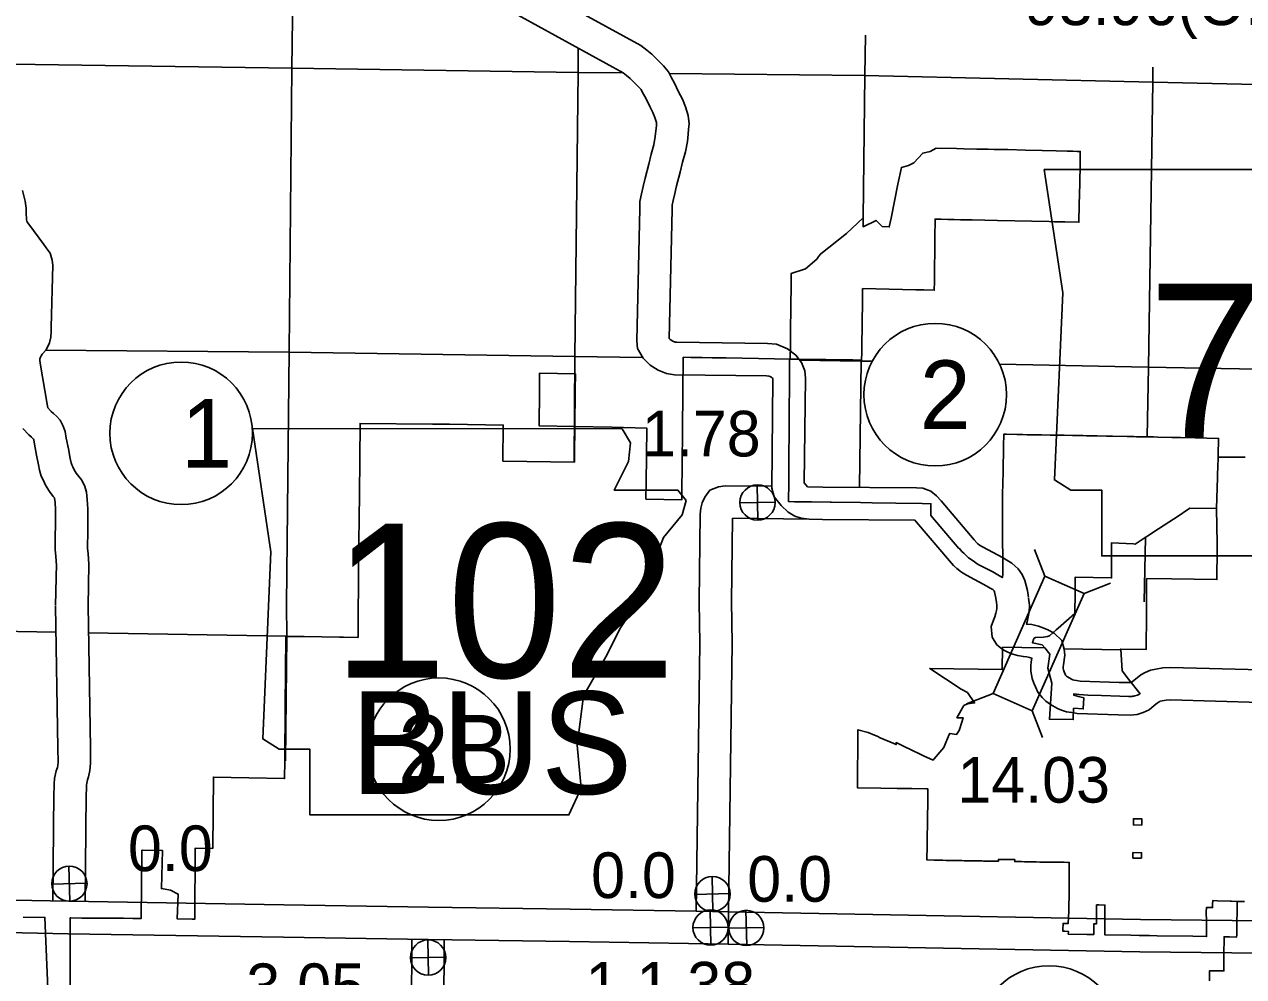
# Model space of a CAD drawing. Extents: x 77230 to 630905, y 790554 to 1662844.
# Drawn here: x 197917 to 220497, y 1585968 to 1603602 of the extents above; entities that cross this region are included whole.
import ezdxf

# ---------------------------------------------------------------- set-up
doc = ezdxf.new("R2010")
doc.units = 0
for name, color, linetype in [('Level 12', 7, 'Continuous'), ('Level 16', 7, 'Continuous'), ('Level 19', 7, 'Continuous'), ('Level 22', 7, 'Continuous'), ('Level 24', 7, 'Continuous'), ('Level 31', 7, 'Continuous'), ('Level 32', 7, 'Continuous'), ('Level 33', 7, 'Continuous'), ('Level 34', 7, 'Continuous')]:
    doc.layers.add(name, color=color, linetype=linetype)

msp = doc.modelspace()

# ---------------------------------------------------------------- linework, layer by layer
at = {"layer": 'Level 12'}
for points in [[(213423, 1597384), (213259, 1597387), (213145, 1597389), (213049, 1597390), (212953, 1597392), (212858, 1597393), (212761, 1597394), (212665, 1597396), (212569, 1597397), (212229, 1597403), (212101, 1597404), (212102, 1597448), (212104, 1597630), (212105, 1597762), (212106, 1597903), (212107, 1597998), (212108, 1598092), (212109, 1598197), (212111, 1598387), (212112, 1598427), (212115, 1598727), (212117, 1598986), (212384, 1599074), (212593, 1599257), (212618, 1599290), (212626, 1599301), (212666, 1599353), (213141, 1599728), (213452, 1600022), (213450, 1599854), (213689, 1599972), (213806, 1599862), (213934, 1599852), (213967, 1600015), (214096, 1600641), (214160, 1600952), (214292, 1600986), (214387, 1601038), (214555, 1601218), (214691, 1601250), (214801, 1601308), (215179, 1601301), (215314, 1601298), (215554, 1601293), (215661, 1601291), (215768, 1601289), (215875, 1601287), (216128, 1601282), (216132, 1601282), (216460, 1601274), (216769, 1601266), (217023, 1601260), (217231, 1601255), (217333, 1601252), (217415, 1601250), (217470, 1601249), (217468, 1601019), (217461, 1600655), (217453, 1600264), (217447, 1599939), (217184, 1599944), (217165, 1599945), (216996, 1599948), (216896, 1599950), (215937, 1599970), (215467, 1599980), (215346, 1599983), (215251, 1599985), (215137, 1599987), (215022, 1599990), (214895, 1599992), (214783, 1599995), (214783, 1599935), (214782, 1599895), (214781, 1599747), (214779, 1599598), (214778, 1599532), (214778, 1599449), (214776, 1599301), (214775, 1599190), (214774, 1599131), (214774, 1599094), (214771, 1598858), (214771, 1598839), (214769, 1598680), (214576, 1598684), (214427, 1598688), (213439, 1598710), (213436, 1598348), (213434, 1598194), (213434, 1598101), (213433, 1598046), (213432, 1598008), (213431, 1597915), (213429, 1597770), (213427, 1597636), (213425, 1597522), (213423, 1597389)], [(208112, 1596158), (207448, 1596170), (207455, 1596818), (207458, 1597144), (208122, 1597132), (208118, 1596835), (208118, 1596808)], [(218614, 1588772), (218614, 1588828), (218615, 1588888), (218457, 1588891), (218457, 1588868), (218456, 1588831), (218455, 1588776)], [(218606, 1588160), (218607, 1588232), (218607, 1588261), (218448, 1588265), (218446, 1588170), (218446, 1588164)]]:
    msp.add_lwpolyline(points, close=True, dxfattribs=at)
for points in [[(208112, 1596158), (208794, 1596141), (209445, 1596124), (209432, 1595105), (209428, 1594810), (210090, 1594797), (210091, 1594854), (210092, 1594965), (210097, 1595436), (210104, 1596114), (210111, 1596773), (210118, 1597439), (210262, 1597436), (210472, 1597432), (210655, 1597429), (210773, 1597426), (210814, 1597426), (210915, 1597424), (211807, 1597408), (212086, 1597402), (212085, 1597136), (212084, 1597033), (212081, 1596338), (212079, 1596082), (212079, 1596051), (212076, 1595604), (212074, 1595123), (212071, 1594764), (212180, 1594763), (212295, 1594761), (212497, 1594759), (212838, 1594755), (212863, 1594754), (213402, 1594748), (213620, 1594744), (214057, 1594736), (214545, 1594727), (214706, 1594724), (214706, 1594636), (214705, 1594510), (215225, 1593897), (215229, 1593901), (215280, 1593841), (215315, 1593810), (215404, 1593721), (215467, 1593679), (215581, 1593600), (215855, 1593462), (215976, 1593392), (216030, 1593358), (216037, 1593422), (216035, 1593784), (216033, 1594004), (216033, 1594055), (216031, 1594297), (216030, 1594455), (216030, 1594601), (216029, 1594639), (216029, 1594700), (216033, 1594905), (216036, 1595102), (216041, 1595322), (216042, 1595372), (216043, 1595419), (216048, 1595686), (216050, 1595790), (216054, 1596012), (216105, 1596011), (216297, 1596008), (216410, 1596006), (216488, 1596004), (216684, 1596001), (216753, 1596000), (216912, 1595997), (216954, 1595997), (216970, 1595996), (217017, 1595995), (217075, 1595994), (217176, 1595993), (217326, 1595990), (217518, 1595987), (217587, 1595985), (217671, 1595984), (217786, 1595981), (217958, 1595978), (218066, 1595976), (218339, 1595971), (218463, 1595968), (218512, 1595967), (218719, 1595963), (218763, 1595962), (218827, 1595961), (218911, 1595959), (219166, 1595954), (219185, 1595953), (219327, 1595950), (219599, 1595944), (220034, 1595935), (220025, 1595619), (220024, 1595588)], [(198763, 1585741), (198763, 1586404), (198763, 1587054), (198780, 1587054), (198979, 1587053), (199093, 1587052), (199302, 1587051), (199421, 1587050), (199750, 1587048), (199924, 1587047), (200080, 1587046), (200093, 1588307), (200102, 1588307), (200474, 1588305), (200456, 1587598), (200621, 1587568), (200762, 1587498), (200748, 1587036), (201022, 1587031), (201073, 1587030), (201078, 1588346), (201406, 1588342), (201419, 1589664), (202076, 1589650), (202737, 1589636), (202740, 1589969), (202747, 1590970), (202762, 1592269), (203425, 1592259), (203829, 1592253), (204098, 1592249), (204101, 1592758), (204104, 1593171), (204106, 1593576), (204125, 1594899), (204129, 1595549), (204133, 1596212), (205473, 1596201), (205790, 1596196), (206455, 1596187), (206786, 1596182), (206778, 1595514), (208105, 1595492), (208107, 1595685), (208111, 1596094), (208112, 1596158)], [(220024, 1595588), (220018, 1595390), (220015, 1595286), (220013, 1595213), (219997, 1594636), (219503, 1594642), (219245, 1594473), (219197, 1594442), (219027, 1594330), (218919, 1594260), (218724, 1594132), (218706, 1594120), (218675, 1594099), (218490, 1593979), (218460, 1593980), (218051, 1594004), (218051, 1593888), (218052, 1593352), (217377, 1593364), (217375, 1593084), (217372, 1592690), (217063, 1592421), (217025, 1592388), (216901, 1592280), (216862, 1592266), (216791, 1592255), (216643, 1592249), (216616, 1592234), (216608, 1592212), (216585, 1592152), (216585, 1592152), (216768, 1592112), (216814, 1592057), (216389, 1592063), (216032, 1592069), (216026, 1591658), (214685, 1591676), (215266, 1591289), (215384, 1591227), (215514, 1591037), (215382, 1591019), (215317, 1590986), (215186, 1590761), (215304, 1590759), (215242, 1590565), (215229, 1590524), (215180, 1590454), (215055, 1590473), (215045, 1590452), (214984, 1590306), (214943, 1590208), (214872, 1590127), (214764, 1589999), (214745, 1589977), (214568, 1590058), (214522, 1590080), (214494, 1590093), (214363, 1590157), (214197, 1590237), (214061, 1590303), (214063, 1590264), (214016, 1590285), (213769, 1590393), (213721, 1590413), (213708, 1590419), (213659, 1590439), (213546, 1590487), (213354, 1590541), (213351, 1590147), (213349, 1589818), (213347, 1589463), (213778, 1589457), (214078, 1589453), (214354, 1589449), (214623, 1589446), (214651, 1589445), (214649, 1589338), (214648, 1589275), (214647, 1589211), (214646, 1589148), (214646, 1589086), (214645, 1589022), (214644, 1588959), (214643, 1588896), (214642, 1588833), (214641, 1588790), (214641, 1588770), (214640, 1588723), (214640, 1588707), (214639, 1588644), (214638, 1588581), (214637, 1588517), (214636, 1588454), (214635, 1588391), (214634, 1588332), (214634, 1588303), (214632, 1588223), (214632, 1588130), (214766, 1588127), (214859, 1588124)], [(220006, 1593737), (220008, 1593891), (220009, 1593987), (219997, 1594636), (220013, 1595213), (220015, 1595286), (220018, 1595390), (220024, 1595588), (220323, 1595589), (220528, 1595589)], [(214639, 1588644), (214640, 1588707), (214640, 1588723), (214641, 1588770), (214641, 1588790), (214642, 1588833), (214643, 1588896), (214644, 1588959), (214645, 1589022), (214646, 1589086), (214646, 1589148), (214647, 1589211), (214648, 1589275), (214649, 1589338), (214651, 1589445), (214623, 1589446), (214354, 1589449), (214078, 1589453), (213778, 1589457), (213347, 1589463), (213349, 1589818), (213351, 1590147), (213354, 1590541), (213546, 1590487), (213659, 1590439), (213708, 1590419), (213721, 1590413), (213769, 1590393), (214016, 1590285), (214063, 1590264), (214061, 1590303), (214197, 1590237), (214363, 1590157), (214494, 1590093), (214522, 1590080), (214568, 1590058), (214745, 1589977), (214764, 1589999), (214872, 1590127), (214943, 1590208), (214984, 1590306), (215045, 1590452), (215055, 1590473), (215180, 1590454), (215229, 1590524), (215242, 1590565), (215304, 1590759), (215186, 1590761), (215317, 1590986), (215382, 1591019), (215514, 1591037), (215384, 1591227), (215266, 1591289), (214685, 1591676), (216026, 1591658), (216032, 1592069), (216389, 1592063), (216814, 1592057), (216906, 1591937), (216870, 1591681), (216943, 1591404), (216899, 1590735), (217343, 1590728), (217347, 1590938), (217528, 1590926), (217536, 1591131), (217437, 1591158), (217351, 1591181), (217352, 1591203), (217449, 1591190), (217614, 1591183), (217866, 1591173), (218206, 1591161), (218368, 1591154), (218379, 1591154), (218394, 1591154), (218409, 1591155), (218427, 1591157), (218446, 1591159), (218465, 1591163), (218480, 1591166), (218507, 1591174), (218531, 1591183), (218556, 1591195), (218578, 1591206), (218579, 1591207), (218368, 1591474), (218246, 1591629), (218222, 1592034), (218690, 1592025), (218696, 1592694), (218697, 1592857), (218701, 1593340), (219160, 1593334), (220002, 1593321), (220002, 1593362), (220003, 1593467), (220004, 1593557), (220005, 1593647), (220006, 1593737)], [(217250, 1586755), (217251, 1586805), (217251, 1586806), (217184, 1586807), (217149, 1586808), (217150, 1586843), (217153, 1586953), (217250, 1586954), (217258, 1587180), (217260, 1587264), (217262, 1587303), (217263, 1587338), (217266, 1587411), (217269, 1587484), (217269, 1587554), (217269, 1587584), (217269, 1587626), (217269, 1587684), (217269, 1587700), (217269, 1587768), (217269, 1587784), (217269, 1587843), (217269, 1587884), (217269, 1587915), (217269, 1587984), (217269, 1588017), (217269, 1588084), (217239, 1588084), (217174, 1588085), (217158, 1588085), (217109, 1588086), (217076, 1588086), (217043, 1588086), (217005, 1588087), (216979, 1588087), (216935, 1588087), (216915, 1588086), (216864, 1588088), (216849, 1588088), (216793, 1588089), (216785, 1588089), (216722, 1588090), (216720, 1588090), (216655, 1588092), (216652, 1588092), (216590, 1588093), (216581, 1588093), (216523, 1588094), (216510, 1588095), (216453, 1588096), (216439, 1588096), (216384, 1588097), (216368, 1588097), (216319, 1588098), (216297, 1588099), (216257, 1588099), (216257, 1588136), (216227, 1588136), (216184, 1588137), (216156, 1588137), (216117, 1588137), (216058, 1588138), (216029, 1588139), (215957, 1588140), (215957, 1588106), (215892, 1588105), (215807, 1588105), (215780, 1588107), (215759, 1588107), (215714, 1588109), (215679, 1588109), (215648, 1588110), (215602, 1588111), (215582, 1588111), (215519, 1588111), (215452, 1588113), (215439, 1588113), (215386, 1588114), (215359, 1588114), (215320, 1588115), (215279, 1588116), (215253, 1588117), (215192, 1588117), (215187, 1588117), (215157, 1588117), (215123, 1588118), (215058, 1588119), (214990, 1588121), (214925, 1588123), (214859, 1588124), (214766, 1588127), (214632, 1588130), (214632, 1588223), (214634, 1588303), (214634, 1588332), (214635, 1588391), (214636, 1588454), (214637, 1588517), (214638, 1588581), (214639, 1588644)], [(214859, 1588124), (214925, 1588123), (214990, 1588121), (215058, 1588119), (215123, 1588118), (215157, 1588117), (215187, 1588117), (215192, 1588117), (215253, 1588117), (215279, 1588116), (215320, 1588115), (215359, 1588114), (215386, 1588114), (215439, 1588113), (215452, 1588113), (215519, 1588111), (215582, 1588111), (215602, 1588111), (215648, 1588110), (215679, 1588109), (215714, 1588109), (215759, 1588107), (215780, 1588107), (215807, 1588105), (215892, 1588105), (215957, 1588106), (215957, 1588140), (216029, 1588139), (216058, 1588138), (216117, 1588137), (216156, 1588137), (216184, 1588137), (216227, 1588136), (216257, 1588136), (216257, 1588099), (216297, 1588099), (216319, 1588098), (216368, 1588097), (216384, 1588097), (216439, 1588096), (216453, 1588096), (216510, 1588095), (216523, 1588094), (216581, 1588093), (216590, 1588093), (216652, 1588092), (216655, 1588092), (216720, 1588090), (216722, 1588090), (216785, 1588089), (216793, 1588089), (216849, 1588088), (216864, 1588088), (216915, 1588086), (216935, 1588087), (216979, 1588087), (217005, 1588087), (217043, 1588086), (217076, 1588086), (217109, 1588086), (217158, 1588085), (217174, 1588085), (217239, 1588084), (217269, 1588084), (217269, 1588017), (217269, 1587984), (217269, 1587915), (217269, 1587884), (217269, 1587843), (217269, 1587784), (217269, 1587768), (217269, 1587700), (217269, 1587684), (217269, 1587626), (217269, 1587584), (217269, 1587554), (217269, 1587484), (217266, 1587411), (217263, 1587338), (217262, 1587303), (217260, 1587264), (217258, 1587180), (217250, 1586954), (217153, 1586953), (217150, 1586843), (217149, 1586808), (217184, 1586807), (217251, 1586806), (217251, 1586805), (217250, 1586755), (217596, 1586748), (217721, 1586746), (217722, 1586944), (217771, 1586943), (217771, 1587022), (217772, 1587122), (217773, 1587297), (217818, 1587296), (217818, 1587296), (217918, 1587294)], [(220511, 1587357), (220459, 1587359), (220380, 1587361), (220373, 1587361), (220273, 1587364), (220247, 1587365), (220012, 1587372), (219924, 1587375), (219922, 1587309), (219921, 1587246), (219824, 1587248), (219807, 1587245), (219806, 1587165), (219806, 1587155), (219808, 1587000), (219810, 1586711), (219554, 1586715), (218896, 1586725), (218756, 1586728), (218598, 1586730), (218562, 1586731), (218409, 1586734), (217924, 1586742), (217925, 1586941), (217926, 1587008), (217926, 1587008), (217927, 1587115), (217927, 1587118), (217927, 1587199), (217928, 1587294), (217918, 1587294), (217818, 1587296), (217818, 1587296), (217773, 1587297), (217772, 1587122), (217771, 1587022), (217771, 1586943), (217722, 1586944), (217721, 1586746), (217596, 1586748), (217250, 1586755)], [(217918, 1587294), (217928, 1587294), (217927, 1587199), (217927, 1587118), (217927, 1587115), (217926, 1587008), (217926, 1587008), (217925, 1586941), (217924, 1586742), (218409, 1586734), (218562, 1586731), (218598, 1586730), (218756, 1586728), (218896, 1586725), (219554, 1586715), (219810, 1586711), (219808, 1587000), (219806, 1587155), (219806, 1587165), (219807, 1587245), (219824, 1587248), (219921, 1587246), (219922, 1587309), (219924, 1587375), (220012, 1587372), (220247, 1587365), (220273, 1587364), (220373, 1587361), (220380, 1587361), (220370, 1586791), (220369, 1586741), (220368, 1586700), (220235, 1586703), (220134, 1586705), (220131, 1586360), (220132, 1586075), (219866, 1586077), (219865, 1585890)], [(197896, 1587071), (198296, 1587064), (198352, 1585750)]]:
    msp.add_lwpolyline(points, dxfattribs=at)
at = {"layer": 'Level 16'}
for points in [[(202774, 1592862), (202822, 1597553), (202869, 1602788), (202947, 1608360)], [(213449, 1600020), (213483, 1602656), (213494, 1603402)], [(208173, 1603158), (208172, 1602708), (208112, 1597445), (208096, 1595493)], [(197244, 1602871), (202871, 1602794), (208170, 1602710), (209003, 1602702)], [(218817, 1602810), (218813, 1602532), (218735, 1597256), (218712, 1595964)], [(209864, 1602693), (213477, 1602658), (218819, 1602534), (220731, 1602490)], [(198311, 1597567), (202822, 1597535), (208110, 1597451), (209359, 1597431)], [(212263, 1597386), (213411, 1597368), (213616, 1597364)], [(213385, 1595036), (213415, 1597368), (213415, 1597385)], [(215983, 1597312), (218725, 1597252), (220761, 1597220)], [(218679, 1594102), (218657, 1592906)], [(202754, 1589967), (202779, 1592266), (202774, 1592862)], [(198505, 1592347), (197072, 1592372)], [(204077, 1592249), (202769, 1592272), (199107, 1592336)], [(218222, 1592022), (217165, 1592041)]]:
    msp.add_lwpolyline(points, dxfattribs=at)
at = {"layer": 'Level 19'}
for p, q in [((216817, 1593385), (216626, 1593877)), ((217542, 1593065), (218034, 1593256)), ((215858, 1591211), (215366, 1591020)), ((216583, 1590891), (216774, 1590399))]:
    msp.add_line(p, q, dxfattribs=at)
msp.add_lwpolyline([(216583, 1590891), (217542, 1593065), (216817, 1593385), (215858, 1591211)], close=True, dxfattribs=at)
at = {"layer": 'Level 22'}
msp.add_line((212186, 1594497), (212300, 1594458), dxfattribs=at)
for points in [[(206785, 1604611), (209334, 1603210), (209446, 1603124), (209538, 1603048), (209652, 1602936), (209753, 1602834), (209848, 1602721), (209899, 1602614), (209957, 1602512), (210033, 1602354), (210104, 1602218), (210158, 1602078), (210212, 1601915), (210230, 1601763), (210219, 1601659), (210210, 1601567), (210195, 1601434), (210158, 1601239), (210107, 1601051), (210062, 1600866), (209994, 1600611), (209963, 1600469), (209934, 1600340), (209916, 1600253), (209914, 1600174), (209861, 1597783), (209879, 1597766), (209928, 1597735), (209968, 1597719), (209998, 1597715), (211678, 1597691), (211848, 1597682), (212052, 1597593), (212203, 1597474), (212306, 1597339), (212369, 1597186), (212381, 1597052), (212361, 1595115), (212422, 1595040)], [(206487, 1604091), (209005, 1602706), (209071, 1602656), (209135, 1602602), (209230, 1602510), (209310, 1602429), (209339, 1602394), (209365, 1602338), (209425, 1602233), (209498, 1602083), (209556, 1601972), (209592, 1601876), (209623, 1601783), (209626, 1601759), (209622, 1601722), (209613, 1601630), (209601, 1601523), (209572, 1601374), (209525, 1601200), (209480, 1601013), (209411, 1600754), (209377, 1600599), (209347, 1600464), (209318, 1600323), (209314, 1600190), (209260, 1597744), (209271, 1597602), (209374, 1597420), (209509, 1597289), (209652, 1597201), (209809, 1597134), (209954, 1597115), (211659, 1597091), (211709, 1597088), (211741, 1597074), (211772, 1597050), (211779, 1597040), (211780, 1597029), (211760, 1595016), (211802, 1594851), (211932, 1594691), (212064, 1594569), (212186, 1594497)], [(199112, 1593603), (199096, 1593795), (199088, 1593903), (199087, 1593997), (199089, 1594132), (199094, 1594304), (199092, 1594631), (199082, 1594802), (199068, 1594939), (199038, 1595042), (198979, 1595159), (198923, 1595229), (198878, 1595290), (198836, 1595355), (198812, 1595409), (198793, 1595447), (198783, 1595485), (198767, 1595564), (198732, 1595742), (198693, 1595940), (198671, 1596065), (198635, 1596162), (198581, 1596270), (198512, 1596346), (198457, 1596398), (198415, 1596436), (198350, 1596503), (198336, 1596568), (198216, 1597294), (198205, 1597376), (198205, 1597406), (198207, 1597420), (198216, 1597442), (198229, 1597467), (198248, 1597494), (198320, 1597575), (198381, 1597703), (198405, 1597811), (198412, 1597912), (198414, 1597998), (198444, 1599140), (198432, 1599234), (198393, 1599367), (198318, 1599463), (198278, 1599524), (197999, 1599900), (197972, 1599935), (197972, 1599936), (197965, 1599955), (197958, 1599982), (197954, 1600015), (197950, 1600086), (197947, 1600200), (197930, 1600327), (197882, 1600528)], [(198513, 1593581), (198498, 1593746), (198488, 1593879), (198487, 1593997), (198489, 1594143), (198494, 1594311), (198492, 1594612), (198484, 1594754), (198477, 1594823), (198472, 1594832), (198448, 1594862), (198384, 1594949), (198305, 1595071), (198268, 1595157), (198230, 1595234), (198199, 1595344), (198179, 1595446), (198143, 1595627), (198104, 1595829), (198089, 1595908), (198084, 1595923), (198082, 1595927), (198049, 1595958), (197998, 1596004), (197888, 1596118)], [(211769, 1595048), (210896, 1595056), (210772, 1595037), (210614, 1594977), (210516, 1594847), (210468, 1594740), (210446, 1594641), (210435, 1594533), (210414, 1592917)], [(212422, 1595040), (212706, 1595034), (214440, 1595018), (214558, 1595011), (214706, 1594956), (214811, 1594870), (214893, 1594778), (215508, 1594055), (215556, 1594000), (215573, 1593983), (215606, 1593958), (215661, 1593926), (216041, 1593722), (216112, 1593679), (216205, 1593624), (216322, 1593522), (216395, 1593412), (216448, 1593305), (216472, 1593213), (216495, 1593121), (216514, 1592988)], [(212454, 1594441), (211034, 1594455), (211014, 1592909)], [(212300, 1594458), (212450, 1594439), (212697, 1594434), (214410, 1594418), (214441, 1594383), (215053, 1593665), (215122, 1593584), (215185, 1593525), (215272, 1593459), (215366, 1593403), (215744, 1593200), (215805, 1593163), (215852, 1593135), (215868, 1593121), (215875, 1593111), (215883, 1593095), (215891, 1593064), (215905, 1593007), (215920, 1592904)], [(198512, 1593615), (198496, 1592840)], [(199112, 1593603), (199096, 1592828)], [(210415, 1592908), (210428, 1592139), (210358, 1587179), (208024, 1587217), (205404, 1587257), (202724, 1587298), (198741, 1587363), (197026, 1587396)], [(198496, 1592829), (198539, 1590196), (198542, 1589940), (198537, 1589878), (198529, 1589843), (198505, 1589781), (198476, 1589635), (198468, 1589540), (198468, 1589464), (198460, 1589368), (198445, 1587373)], [(199096, 1592839), (199139, 1590204), (199142, 1589920), (199132, 1589786), (199104, 1589669), (199084, 1589615), (199071, 1589548), (199068, 1589515), (199068, 1589443), (199060, 1589343), (199045, 1587358)], [(211014, 1592918), (211028, 1592140), (210955, 1587168)], [(220809, 1591047), (219141, 1591091), (219063, 1591089), (218988, 1591075), (218952, 1591068), (218943, 1591064), (218930, 1591056), (218899, 1591032), (218843, 1590986), (218746, 1590911), (218637, 1590860), (218525, 1590825), (218404, 1590811), (218175, 1590817), (217414, 1590843), (217313, 1590859), (217216, 1590872), (217126, 1590904), (217051, 1590934), (216918, 1591010), (216836, 1591066), (216766, 1591135), (216689, 1591235), (216641, 1591332), (216614, 1591404), (216582, 1591491), (216558, 1591622), (216558, 1591725), (216563, 1591800), (216572, 1591866), (216534, 1591878), (216481, 1591891), (216419, 1591896), (216310, 1591915), (216221, 1591942), (216143, 1591969), (216041, 1592021), (215928, 1592114), (215843, 1592255), (215823, 1592449), (215865, 1592567), (215887, 1592633), (215908, 1592699), (215919, 1592746), (215926, 1592788), (215928, 1592828), (215919, 1592914)], [(220825, 1591647), (219143, 1591691), (219002, 1591688), (218873, 1591664), (218774, 1591643), (218675, 1591602), (218593, 1591554), (218524, 1591501), (218468, 1591455), (218431, 1591426), (218420, 1591420), (218401, 1591415), (218377, 1591412), (218192, 1591417), (217472, 1591441), (217401, 1591452), (217359, 1591458), (217337, 1591466), (217312, 1591476), (217236, 1591519), (217219, 1591531), (217217, 1591533), (217201, 1591553), (217192, 1591571), (217175, 1591615), (217163, 1591649), (217158, 1591677), (217158, 1591706), (217160, 1591739), (217185, 1591923), (217175, 1592029), (217133, 1592190), (216987, 1592329), (216873, 1592390), (216796, 1592423), (216700, 1592455), (216577, 1592486), (216495, 1592492), (216473, 1592496), (216487, 1592540), (216508, 1592628), (216524, 1592723), (216529, 1592847), (216515, 1592978)], [(210955, 1587168), (210358, 1587179)], [(210955, 1587168), (210949, 1586568)], [(220853, 1587001), (218587, 1587027), (213297, 1587124), (210955, 1587168)], [(210949, 1586569), (208015, 1586617), (205395, 1586657), (202714, 1586699), (198730, 1586763), (197017, 1586796)], [(205093, 1586286), (205091, 1586665)], [(205693, 1586288), (205691, 1586660)], [(220846, 1586401), (218578, 1586427), (213286, 1586524), (210950, 1586568)], [(205071, 1584549), (205093, 1586291)], [(205671, 1584541), (205693, 1586283)]]:
    msp.add_lwpolyline(points, dxfattribs=at)
at = {"layer": 'Level 24'}
msp.add_line((208992, 1596118), (208992, 1596118), dxfattribs=at)
msp.add_line((208992, 1596118), (208992, 1596118), dxfattribs=at)
for points in [[(216803, 1600915), (217146, 1598631), (216994, 1595167), (217298, 1594977), (217869, 1594977), (217869, 1593759), (222666, 1593759), (222894, 1594254), (222818, 1595053), (222932, 1595967), (223351, 1596690), (223617, 1597223), (223998, 1597794), (224226, 1598403), (224417, 1598898), (224759, 1599316), (224835, 1599583), (224683, 1599773), (223503, 1599773), (223769, 1600306), (223807, 1600649), (223650, 1600912)], [(202140, 1596118), (202483, 1593834), (202331, 1590370), (202635, 1590180), (203206, 1590180), (203206, 1588962), (208002, 1588962), (208231, 1589457), (208155, 1590256), (208269, 1591170), (208687, 1591893), (208954, 1592426), (209335, 1592997), (209563, 1593606), (209753, 1594101), (210096, 1594519), (210172, 1594786), (210020, 1594976), (208840, 1594976), (209106, 1595509), (209144, 1595852), (208986, 1596115)]]:
    msp.add_lwpolyline(points, close=True, dxfattribs=at)
at = {"layer": 'Level 33'}
for centre in [(214785, 1596745), (200820, 1596029), (205594, 1590180), (216894, 1584849)]:
    msp.add_circle(centre, 1320, dxfattribs=at)
at = {"layer": 'Level 34'}
for p, q in [((211503, 1594423), (211488, 1595074)), ((211170, 1594741), (211821, 1594756)), ((198758, 1587363), (198743, 1588014)), ((198425, 1587681), (199076, 1587696)), ((210668, 1587172), (210653, 1587823)), ((210335, 1587490), (210986, 1587505)), ((210632, 1586552), (210617, 1587203)), ((211294, 1586545), (211279, 1587196)), ((210299, 1586870), (210950, 1586885)), ((210961, 1586863), (211612, 1586878)), ((205403, 1585996), (205388, 1586647)), ((205070, 1586314), (205721, 1586329))]:
    msp.add_line(p, q, dxfattribs=at)
for centre in [(211495, 1594748), (198751, 1587689), (210660, 1587497), (210625, 1586877), (211287, 1586870), (205395, 1586321)]:
    msp.add_circle(centre, 326, dxfattribs=at)

# ---------------------------------------------------------------- texts
at = {"layer": 'Level 24'}
for s, height, p in [('72', 2851.2, (218729, 1595950)), ('102', 2851.2, (203624, 1591507)), ('BUS', 1900.8, (203953, 1589349))]:
    msp.add_text(s, height=height, dxfattribs=at).set_placement(p)
at = {"layer": 'Level 31'}
for s, p in [('1.78', (209354, 1595601)), ('0.0', (199835, 1587922)), ('0.0', (208412, 1587423)), ('0.0', (211304, 1587355)), ('1 1.38', (208310, 1585397)), ('3.05', (202027, 1585367))]:
    msp.add_text(s, height=844.8, dxfattribs=at).set_placement(p)
at = {"layer": 'Level 32'}
for s, p in [('93.96(O.P.)', (216444, 1603588)), ('14.03', (215195, 1589190))]:
    msp.add_text(s, height=844.8, dxfattribs=at).set_placement(p)
at = {"layer": 'Level 33'}
for s, height, p in [('2', 1267, (214501, 1596112)), ('1', 1267, (200820, 1595395)), ('2B', 1267.2, (204834, 1589547))]:
    msp.add_text(s, height=height, dxfattribs=at).set_placement(p)

doc.saveas('drawing.dxf')
